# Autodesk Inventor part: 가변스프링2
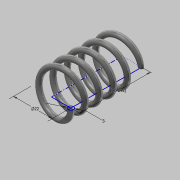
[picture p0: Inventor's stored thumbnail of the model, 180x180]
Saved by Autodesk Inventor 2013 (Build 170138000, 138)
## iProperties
Created: 2015-02
Part Number: 가변스프링2
Material: 강철, 탄소
Document SubType Name: Modeling
Designer: Administrator
Density: 7.87 g/cm^3
Mass: 18.9202 g
Surface Area: 32.5617 cm^2
Volume: 2.40409 cm^3
Author: Administrator
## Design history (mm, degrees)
sketch "스케치1"
  geometry: L1 (0, 0)-(11, 0); L2 (11, 0)-(11, 40.245); L3 (11, 40.245)-(0, 40.245); L4 (0, 40.245)-(0, 0); C1 r 1.5 at (11, 0)
  constraints: 8 end point, 2 parallel, 1 centre point, 1 coincident, 1 horizontal, 1 perpendicular
  dimensions: "d0" = 40.2455 distance of L1.end L2.end (derived); "d2" = 22 diameter of L2 L4; "d3" = 3 diameter of C1
feature "코일1" sketch "스케치1" pitch "d4" = 10; turns "d6" = 5; dims "d5" = 40.2455 (= d0), "d7" = 0, angle "d8" = 90 deg, angle "d9" = 90 deg, "d10" = 0, "d11" = 0
node "작업 평면1"
sketch "스케치2"
  geometry: L1 (-12.5, 0)-(-9.5, 0) reference; L2 (-12.5, 0)-(-9.5, 0) reference; 1 further point
  constraints: 2 horizontal alignment
extrude "돌출1" cut sketch "스케치2" distance "d13" = 10; taper "d14" = 0 deg
node "작업 평면2"
sketch "스케치3"
  geometry: L1 (-9.5, 0)-(-12.5, 0) reference; 1 further point
  constraints: 1 horizontal alignment
extrude "돌출2" cut sketch "스케치3" distance "d16" = 10; taper "d17" = 0 deg
node "솔리드1"
node "절단 모서리 투영1"
node "절단 모서리 투영2"
node "절단 모서리 투영3"
other parameters: "d12" = 0, "d15" = 40.2455 (= d0)
